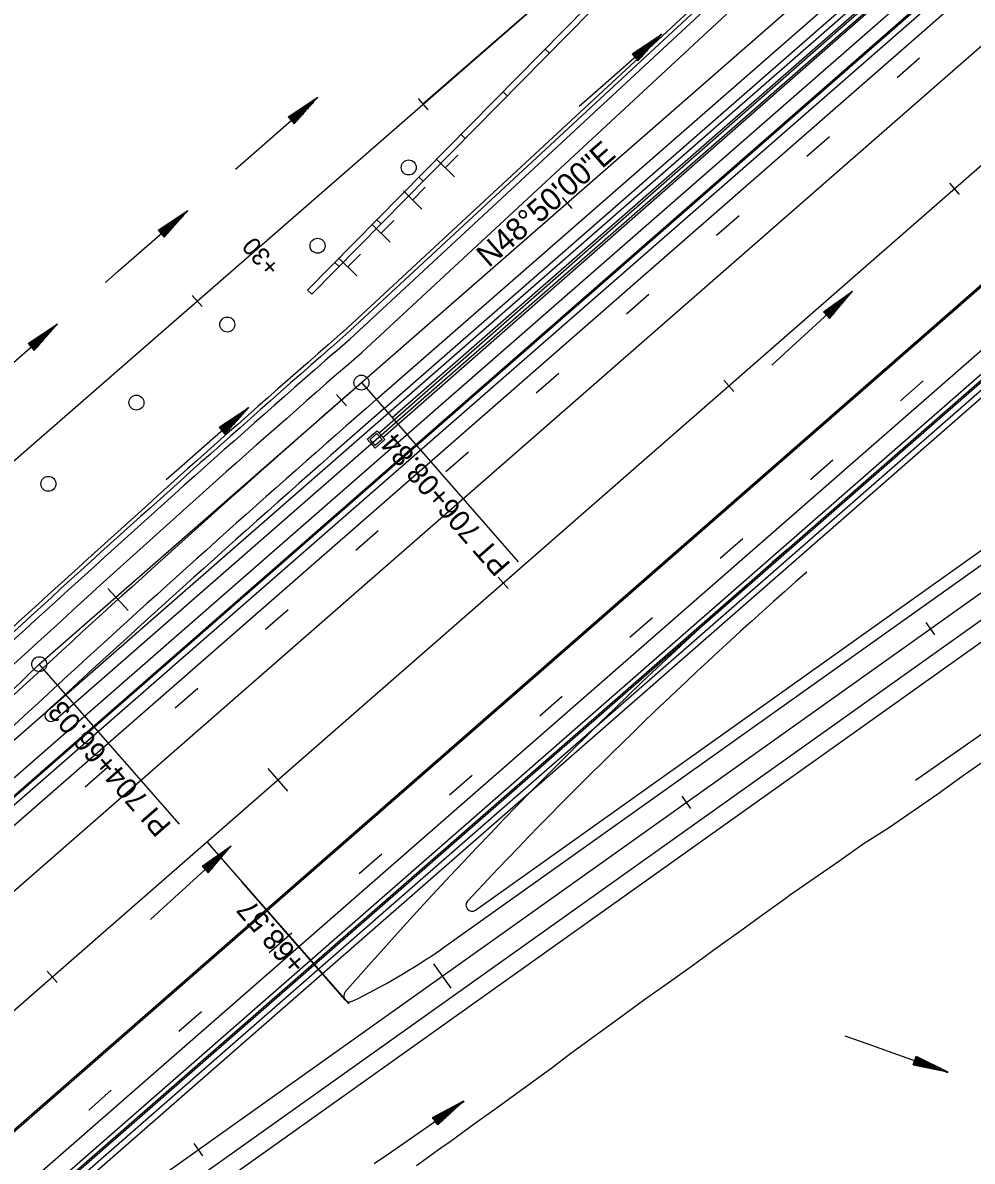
# Model space of a CAD drawing. Extents: x 1300404 to 1323571, y 234004 to 252077.
# Drawn here: x 1309471.7 to 1309788.6, y 239796.9 to 240177.2 of the extents above; entities that cross this region are included whole.
import ezdxf

# ---------------------------------------------------------------- set-up
doc = ezdxf.new("R2010")
doc.units = 0
for name, color, linetype in [('R_Barrel', 7, 'Continuous'), ('R_Barrier Wall', 7, 'Continuous'), ('R_Const Limits', 7, 'Continuous'), ('R_Draft', 7, 'Continuous'), ('R_Drop Inlet', 7, 'Continuous'), ('R_Flow Arrows', 7, 'Continuous'), ('R_Horz Alg Annot', 7, 'Continuous'), ('R_Horz Alg Annot Leader', 7, 'Continuous'), ('R_Horz Alg Major Ticks', 7, 'Continuous'), ('R_Horz Alg Minor Ticks', 7, 'Continuous'), ('R_Horz Alg Tangents', 7, 'Continuous'), ('R_Horz Alg Tangents Text', 7, 'Continuous'), ('R_Lane Edge', 7, 'Continuous'), ('R_Pipe Culvert', 7, 'Continuous'), ('R_Proposed', 7, 'Continuous'), ('R_Shoulder', 7, 'Continuous'), ('R_Temp Barrier Wall', 7, 'Continuous'), ('R_Temp Travel Lane', 7, 'Continuous'), ('R_Temp Travel Stripe', 7, 'Continuous')]:
    doc.layers.add(name, color=color, linetype=linetype)

msp = doc.modelspace()

# ---------------------------------------------------------------- linework, layer by layer
at = {"layer": 'R_Barrel'}
for p, q in [((1309612.7, 240128.71), (1309616.92, 240132.97)), ((1309615.74, 240125.7), (1309609.63, 240131.76)), ((1309604.82, 240114.97), (1309598.71, 240121.03)), ((1309601.78, 240117.99), (1309606, 240122.25)), ((1309594.32, 240103.86), (1309588.21, 240109.91)), ((1309591.28, 240106.87), (1309595.5, 240111.13)), ((1309583.18, 240092.62), (1309577.07, 240098.68)), ((1309580.14, 240095.63), (1309584.36, 240099.89))]:
    msp.add_line(p, q, dxfattribs=at)
for centre in [(1309600.5, 240128.86), (1309570.05, 240102.71), (1309539.93, 240076.4), (1309509.61, 240050.3), (1309480.2, 240023.19)]:
    msp.add_circle(centre, 2.5, dxfattribs=at)
at = {"layer": 'R_Barrier Wall'}
for p, q in [((1309593.62, 240046.84), (1310923.44, 241209.65)), ((1309594.93, 240045.34), (1310924.76, 241208.15)), ((1309578.59, 240073.99), (1309787.17, 240267.71)), ((1309579.5, 240073.02), (1309788.07, 240266.74)), ((1309573.63, 240069.66), (1309578.62, 240074.02)), ((1309574.51, 240068.65), (1309579.5, 240073.02)), ((1309593.62, 240046.84), (1309594.93, 240045.34))]:
    msp.add_line(p, q, dxfattribs=at)
for centre, radius in [((1313356.22, 235743.77), 5746.41), ((1313356.24, 235743.79), 5745.08)]:
    msp.add_arc(centre, radius, 131.166667, 134.023463, dxfattribs=at)
at = {"layer": 'R_Const Limits'}
for points in [[(1309793.39, 239931.15), (1309785.2, 239925.42), (1309777.1, 239919.54), (1309768.93, 239913.79), (1309760.64, 239908.18), (1309752.21, 239902.79), (1309744.02, 239897.05), (1309735.79, 239891.37), (1309727.59, 239885.64), (1309726.44, 239884.81), (1309719.49, 239879.77), (1309711.38, 239873.92), (1309703.27, 239868.07), (1309695.17, 239862.21), (1309687.07, 239856.34), (1309678.89, 239850.58), (1309670.8, 239844.71), (1309662.71, 239838.83), (1309654.64, 239832.92), (1309647.76, 239827.69), (1309646.66, 239826.89), (1309638.6, 239820.97), (1309630.5, 239815.11), (1309622.38, 239809.27), (1309614.27, 239803.42), (1309611.24, 239801.23)], [(1309793.39, 239931.15), (1309785.2, 239925.42), (1309777.1, 239919.54), (1309768.93, 239913.79), (1309760.64, 239908.18), (1309752.21, 239902.79), (1309744.02, 239897.05), (1309735.79, 239891.37), (1309727.59, 239885.64), (1309726.44, 239884.81), (1309719.49, 239879.77), (1309711.38, 239873.92), (1309703.27, 239868.07), (1309695.17, 239862.21), (1309687.07, 239856.34), (1309678.89, 239850.58), (1309670.8, 239844.71), (1309662.71, 239838.83), (1309654.64, 239832.92), (1309647.76, 239827.69), (1309646.66, 239826.89), (1309638.6, 239820.97), (1309630.5, 239815.11), (1309622.38, 239809.27), (1309614.27, 239803.42), (1309613.83, 239803.11)], [(1309611.24, 239801.23), (1309611.24, 239801.23), (1309603.06, 239795.39)]]:
    msp.add_lwpolyline(points, dxfattribs=at)
at = {"layer": 'R_Draft'}
for p, q in [((1308396.96, 238971.92), (1312368.36, 242444.53)), ((1308407.83, 238959.5), (1312379.22, 242432.11)), ((1308447.32, 238914.33), (1312418.71, 242386.94)), ((1308458.18, 238901.91), (1312429.57, 242374.52)), ((1309184.47, 239689.08), (1312131.36, 242265.86)), ((1309037.78, 239548.19), (1312137.61, 242258.71)), ((1309193.69, 239678.54), (1312140.58, 242255.32)), ((1309413.86, 239721.62), (1312065.67, 242040.38)), ((1309410.89, 239725), (1311987.97, 241978.41)), ((1309410.89, 239725), (1311987.97, 241978.41)), ((1309533.11, 239903.6), (1309580.46, 239849.45))]:
    msp.add_line(p, q, dxfattribs=at)
at = {"layer": 'R_Drop Inlet'}
for p, q in [((1309586.67, 240038.06), (1309589.94, 240040.91)), ((1309586.67, 240038.06), (1309589.94, 240040.91)), ((1309589.94, 240040.91), (1309592.52, 240037.95)), ((1309589.94, 240040.91), (1309592.52, 240037.95)), ((1309589.25, 240035.1), (1309586.67, 240038.06)), ((1309589.25, 240035.1), (1309586.67, 240038.06)), ((1309587.61, 240038), (1309589.87, 240039.97)), ((1309587.61, 240038), (1309589.87, 240039.97)), ((1309589.32, 240036.04), (1309587.61, 240038)), ((1309589.32, 240036.04), (1309587.61, 240038)), ((1309592.52, 240037.95), (1309589.25, 240035.1)), ((1309592.52, 240037.95), (1309589.25, 240035.1)), ((1309591.58, 240038.01), (1309589.32, 240036.04)), ((1309591.58, 240038.01), (1309589.32, 240036.04)), ((1309589.87, 240039.97), (1309591.58, 240038.01)), ((1309589.87, 240039.97), (1309591.58, 240038.01))]:
    msp.add_line(p, q, dxfattribs=at)
at = {"layer": 'R_Flow Arrows'}
for p, q in [((1309675.04, 240166.84), (1309684.93, 240173.35)), ((1309677.02, 240164.53), (1309684.93, 240173.35)), ((1309675.04, 240166.84), (1309677.02, 240164.53)), ((1309560.29, 240145.75), (1309570.15, 240152.32)), ((1309562.29, 240143.46), (1309570.15, 240152.32)), ((1309560.29, 240145.75), (1309562.29, 240143.46)), ((1309516.86, 240107.89), (1309526.72, 240114.47)), ((1309518.86, 240105.6), (1309526.72, 240114.47)), ((1309516.86, 240107.89), (1309518.86, 240105.6)), ((1309738.91, 240080.67), (1309748.59, 240087.5)), ((1309740.96, 240078.43), (1309748.59, 240087.5)), ((1309738.91, 240080.67), (1309740.96, 240078.43)), ((1309473.44, 240070.03), (1309483.29, 240076.61)), ((1309475.43, 240067.74), (1309483.29, 240076.61)), ((1309473.44, 240070.03), (1309475.43, 240067.74)), ((1309537.17, 240042.13), (1309547.07, 240048.64)), ((1309539.15, 240039.82), (1309547.07, 240048.64)), ((1309537.17, 240042.13), (1309539.15, 240039.82)), ((1309531.49, 239895.49), (1309541.17, 239902.31)), ((1309533.55, 239893.25), (1309541.17, 239902.31)), ((1309531.49, 239895.49), (1309533.55, 239893.25)), ((1309768.88, 239829.11), (1309769.87, 239831.99)), ((1309769.87, 239831.99), (1309780.49, 239826.73)), ((1309768.88, 239829.11), (1309780.49, 239826.73)), ((1309608.4, 239811.51), (1309618.85, 239817.09)), ((1309610.16, 239809.04), (1309618.85, 239817.09)), ((1309610.16, 239809.04), (1309608.4, 239811.51))]:
    msp.add_line(p, q, dxfattribs=at)
for points in [[(1309657.43, 240149.36), (1309661.75, 240153.18), (1309684.83, 240173.46)], [(1309675.63, 240166.15), (1309680.34, 240170.2), (1309680.98, 240170.74)], [(1309675.83, 240165.92), (1309680.54, 240169.97), (1309682.96, 240172.04)], [(1309676.23, 240165.46), (1309680.94, 240169.51), (1309683.36, 240171.58)], [(1309675.23, 240166.61), (1309677.02, 240168.14)], [(1309675.43, 240166.38), (1309679, 240169.44)], [(1309676.42, 240165.22), (1309681.14, 240169.28), (1309681.77, 240169.82)], [(1309676.62, 240164.99), (1309680.19, 240168.06)], [(1309676.82, 240164.76), (1309678.6, 240166.3)], [(1309542.65, 240128.33), (1309546.98, 240132.13), (1309570.15, 240152.32)], [(1309561.09, 240144.83), (1309565.78, 240148.92), (1309568.18, 240151)], [(1309560.69, 240145.29), (1309564.23, 240148.38)], [(1309560.89, 240145.06), (1309565.58, 240149.15), (1309566.21, 240149.69)], [(1309561.49, 240144.37), (1309566.18, 240148.46), (1309568.58, 240150.54)], [(1309561.69, 240144.15), (1309566.38, 240148.23), (1309567, 240148.78)], [(1309560.49, 240145.52), (1309562.26, 240147.07)], [(1309561.89, 240143.92), (1309565.43, 240147)], [(1309562.09, 240143.69), (1309563.86, 240145.23)], [(1309499.22, 240090.47), (1309503.56, 240094.28), (1309526.72, 240114.47)], [(1309517.66, 240106.97), (1309522.35, 240111.06), (1309524.75, 240113.14)], [(1309517.06, 240107.66), (1309518.83, 240109.21)], [(1309517.26, 240107.43), (1309520.81, 240110.52)], [(1309517.46, 240107.2), (1309522.15, 240111.29), (1309522.78, 240111.84)], [(1309518.06, 240106.52), (1309522.75, 240110.6), (1309525.15, 240112.68)], [(1309518.26, 240106.29), (1309522.95, 240110.37), (1309523.58, 240110.92)], [(1309518.46, 240106.06), (1309522, 240109.15)], [(1309518.66, 240105.83), (1309520.43, 240107.37)], [(1309721.72, 240062.81), (1309725.95, 240066.72), (1309748.59, 240087.5)], [(1309739.32, 240080.23), (1309742.78, 240083.4)], [(1309739.52, 240080), (1309744.11, 240084.21), (1309744.72, 240084.77)], [(1309739.73, 240079.78), (1309744.31, 240083.98), (1309746.66, 240086.13)], [(1309740.14, 240079.33), (1309744.72, 240083.53), (1309747.07, 240085.68)], [(1309740.35, 240079.11), (1309744.93, 240083.31), (1309745.54, 240083.87)], [(1309739.11, 240080.45), (1309740.84, 240082.04)], [(1309740.55, 240078.88), (1309744.02, 240082.06)], [(1309740.76, 240078.66), (1309742.49, 240080.25)], [(1309455.8, 240052.61), (1309460.13, 240056.42), (1309483.29, 240076.61)], [(1309474.24, 240069.12), (1309478.92, 240073.2), (1309481.33, 240075.29)], [(1309473.64, 240069.8), (1309475.41, 240071.35)], [(1309473.84, 240069.57), (1309477.38, 240072.66)], [(1309474.03, 240069.34), (1309478.72, 240073.43), (1309479.35, 240073.98)], [(1309474.63, 240068.66), (1309479.32, 240072.74), (1309481.72, 240074.83)], [(1309474.83, 240068.43), (1309479.52, 240072.51), (1309480.15, 240073.06)], [(1309475.03, 240068.2), (1309478.58, 240071.29)], [(1309475.23, 240067.97), (1309477.01, 240069.51)], [(1309519.57, 240024.65), (1309523.89, 240028.47), (1309546.97, 240048.75)], [(1309537.57, 240041.67), (1309541.13, 240044.73)], [(1309537.76, 240041.44), (1309542.48, 240045.49), (1309543.11, 240046.03)], [(1309537.96, 240041.2), (1309542.68, 240045.26), (1309545.09, 240047.33)], [(1309538.36, 240040.74), (1309543.07, 240044.8), (1309545.49, 240046.87)], [(1309538.56, 240040.51), (1309543.27, 240044.57), (1309543.9, 240045.11)], [(1309537.37, 240041.9), (1309539.15, 240043.43)], [(1309538.76, 240040.28), (1309542.32, 240043.35)], [(1309538.96, 240040.05), (1309540.74, 240041.58)], [(1309769.69, 239924.25), (1309774.43, 239927.54), (1309799.63, 239945.1)], [(1309514.3, 239877.62), (1309518.54, 239881.54), (1309541.17, 239902.31)], [(1309532.31, 239894.59), (1309536.89, 239898.8), (1309539.24, 239900.94)], [(1309532.72, 239894.14), (1309537.3, 239898.35), (1309539.65, 239900.49)], [(1309531.7, 239895.26), (1309533.43, 239896.85)], [(1309531.9, 239895.04), (1309535.36, 239898.22)], [(1309532.11, 239894.81), (1309536.69, 239899.02), (1309537.3, 239899.58)], [(1309532.93, 239893.92), (1309537.51, 239898.12), (1309538.12, 239898.68)], [(1309533.14, 239893.69), (1309536.6, 239896.87)], [(1309533.34, 239893.47), (1309535.07, 239895.06)], [(1309746.06, 239838.83), (1309751.49, 239836.88), (1309780.43, 239826.58)], [(1309769.77, 239831.7), (1309771.99, 239830.94)], [(1309768.98, 239829.4), (1309771.2, 239828.64)], [(1309769.08, 239829.69), (1309773.52, 239828.16)], [(1309769.18, 239829.98), (1309775.06, 239827.95), (1309775.85, 239827.68)], [(1309769.28, 239830.26), (1309775.16, 239828.24), (1309778.17, 239827.21)], [(1309769.47, 239830.84), (1309775.35, 239828.82), (1309778.36, 239827.79)], [(1309769.57, 239831.13), (1309775.45, 239829.1), (1309776.24, 239828.84)], [(1309769.67, 239831.41), (1309774.12, 239829.88)], [(1309588.99, 239796.12), (1309593.73, 239799.4), (1309618.94, 239816.97)], [(1309608.57, 239811.26), (1309610.49, 239812.63)], [(1309608.75, 239811.02), (1309612.58, 239813.74)], [(1309608.93, 239810.77), (1309613.99, 239814.38), (1309614.67, 239814.86)], [(1309609.1, 239810.52), (1309614.17, 239814.13), (1309616.75, 239815.98)], [(1309609.46, 239810.03), (1309614.52, 239813.63), (1309617.11, 239815.49)], [(1309609.63, 239809.78), (1309614.7, 239813.39), (1309615.37, 239813.87)], [(1309609.81, 239809.53), (1309613.64, 239812.26)], [(1309609.99, 239809.28), (1309611.9, 239810.65)]]:
    msp.add_lwpolyline(points, dxfattribs=at)
at = {"layer": 'R_Horz Alg Annot Leader'}
for q in [(1309544.76, 239890.27), (1309558.71, 239874.31)]:
    msp.add_line((1309579.27, 239850.81), q, dxfattribs=at)
for points in [[(1309584.71, 240056.98), (1309637.02, 239997.16)], [(1309584.71, 240056.98), (1309637.02, 239997.16)], [(1309523.93, 239909.45), (1309477.16, 239962.94)], [(1309523.93, 239909.45), (1309477.16, 239962.94)]]:
    msp.add_lwpolyline(points, dxfattribs=at)
at = {"layer": 'R_Horz Alg Major Ticks'}
for points in [[(1309500.1, 239988.27), (1309506.82, 239980.87)], [(1309500.1, 239988.27), (1309506.82, 239980.87)], [(1309553.48, 239928.05), (1309560.06, 239920.53)], [(1309553.48, 239928.05), (1309560.06, 239920.53)], [(1309608.77, 239862.86), (1309614.57, 239854.71)], [(1309608.77, 239862.86), (1309614.57, 239854.71)]]:
    msp.add_lwpolyline(points, dxfattribs=at)
at = {"layer": 'R_Horz Alg Minor Ticks'}
for points in [[(1309603.59, 240151.85), (1309606.87, 240148.09)], [(1309603.59, 240151.85), (1309606.87, 240148.09)], [(1309780.96, 240123.65), (1309784.26, 240119.88)], [(1309780.96, 240123.65), (1309784.26, 240119.88)], [(1309651.69, 240118.87), (1309654.98, 240115.11)], [(1309651.69, 240118.87), (1309654.98, 240115.11)], [(1309528.21, 240086.14), (1309531.49, 240082.37)], [(1309528.21, 240086.14), (1309531.49, 240082.37)], [(1309705.68, 240057.82), (1309708.98, 240054.06)], [(1309705.68, 240057.82), (1309708.98, 240054.06)], [(1309576.41, 240053.04), (1309579.71, 240049.28)], [(1309576.41, 240053.04), (1309579.71, 240049.28)], [(1309630.4, 239992), (1309633.7, 239988.23)], [(1309630.4, 239992), (1309633.7, 239988.23)], [(1309773.13, 239976.84), (1309776.03, 239972.77)], [(1309773.13, 239976.84), (1309776.03, 239972.77)], [(1309691.67, 239918.83), (1309694.57, 239914.76)], [(1309691.67, 239918.83), (1309694.57, 239914.76)], [(1309479.84, 239860.35), (1309483.14, 239856.58)], [(1309479.84, 239860.35), (1309483.14, 239856.58)], [(1309528.76, 239802.81), (1309531.66, 239798.74)], [(1309528.76, 239802.81), (1309531.66, 239798.74)]]:
    msp.add_lwpolyline(points, dxfattribs=at)
at = {"layer": 'R_Horz Alg Tangents'}
for p, q in [((1309477.16, 239962.94), (1309584.71, 240056.98)), ((1309477.16, 239962.94), (1309584.71, 240056.98)), ((1309374.43, 239863.65), (1309477.16, 239962.94)), ((1309374.43, 239863.65), (1309477.16, 239962.94))]:
    msp.add_line(p, q, dxfattribs=at)
at = {"layer": 'R_Lane Edge'}
for p, q in [((1309254.07, 239731.34), (1311026.82, 241281.45)), ((1309254.07, 239731.34), (1311026.82, 241281.45)), ((1309589.67, 240051.36), (1310894.61, 241192.4)), ((1309584.85, 240067.07), (1309804.77, 240271.32)), ((1309579.77, 240062.63), (1309584.85, 240067.07)), ((1309611.37, 239867.78), (1309830.38, 240023.76)), ((1309374.62, 239680.75), (1309839.08, 240011.54))]:
    msp.add_line(p, q, dxfattribs=at)
for centre, radius, start, end in [((1313356.24, 235743.79), 5737.08, 131.166667, 134.023463), ((1313356.22, 235743.77), 5722.08, 131.16667, 134.02346), ((1313356.22, 235743.77), 5722.08, 131.16667, 134.02346), ((1310770.2, 238812.1), 1582, 131.26805, 138.83378), ((1309486.73, 240046.02), 217.5, 295.8741, 304.9655), ((1309580.77, 239852.13), 2, 138.8331, 295.8874)]:
    msp.add_arc(centre, radius, start, end, dxfattribs=at)
at = {"layer": 'R_Pipe Culvert'}
for p, q in [((1309590.57, 240040.19), (1310077.98, 240468.2)), ((1309590.57, 240040.19), (1310077.98, 240468.2)), ((1309590.57, 240040.19), (1310077.98, 240468.2)), ((1309591.88, 240038.68), (1310079.3, 240466.69)), ((1309591.88, 240038.68), (1310079.3, 240466.69)), ((1309591.88, 240038.68), (1310079.3, 240466.69))]:
    msp.add_line(p, q, dxfattribs=at)
at = {"layer": 'R_Proposed'}
for p, q in [((1308427.57, 238936.91), (1312793.8, 242754.77)), ((1308427.57, 238936.91), (1312793.8, 242754.77)), ((1309180.37, 239595.16), (1312398.96, 242409.52)), ((1309180.37, 239595.16), (1312398.96, 242409.52)), ((1309584.71, 240056.98), (1310889.67, 241198.05)), ((1309584.71, 240056.98), (1310889.67, 241198.05)), ((1309454.47, 240018.55), (1309644.99, 240184.63)), ((1309454.47, 240018.55), (1309644.99, 240184.63)), ((1309644.99, 240184.63), (1309605.23, 240149.97)), ((1309644.99, 240184.63), (1309605.23, 240149.97)), ((1309370.27, 239686.86), (1309834.73, 240017.65)), ((1309370.27, 239686.86), (1309834.73, 240017.65)), ((1309370.27, 239686.86), (1309834.73, 240017.65)), ((1309370.27, 239686.86), (1309834.73, 240017.65)), ((1309370.27, 239686.86), (1309834.73, 240017.65)), ((1309370.27, 239686.86), (1309834.73, 240017.65))]:
    msp.add_line(p, q, dxfattribs=at)
for centre in [(1309584.71, 240056.98), (1309584.71, 240056.98), (1309477.16, 239962.94), (1309477.16, 239962.94)]:
    msp.add_circle(centre, 2.5, dxfattribs=at)
msp.add_arc((1313356.22, 235743.77), 5729.58, 131.166667, 134.023463, dxfattribs=at)
msp.add_arc((1313356.22, 235743.77), 5729.58, 131.166667, 134.023463, dxfattribs=at)
at = {"layer": 'R_Shoulder'}
for p, q in [((1309482.39, 239944.26), (1311020.24, 241288.97)), ((1309482.39, 239944.26), (1311020.24, 241288.97)), ((1309592.3, 240048.35), (1310897.24, 241189.39)), ((1309580.84, 240071.53), (1309800.75, 240275.78)), ((1309575.82, 240067.15), (1309580.84, 240071.53)), ((1309622.76, 239880.8), (1309828.06, 240027.02)), ((1309378.1, 239675.87), (1309842.57, 240006.66))]:
    msp.add_line(p, q, dxfattribs=at)
for centre, radius, start, end in [((1313356.24, 235743.79), 5743.08, 131.166667, 134.023463), ((1313356.24, 235743.79), 5718.08, 131.16667, 132.68298), ((1313356.24, 235743.79), 5718.08, 131.16667, 132.68298), ((1310770.2, 238812.1), 1572, 131.26805, 137.02024), ((1309481.07, 239945.77), 2, 132.683, 311.1667), ((1309481.07, 239945.77), 2, 132.683, 311.1667), ((1309621.6, 239882.43), 2, 137.0202, 305.4583)]:
    msp.add_arc(centre, radius, start, end, dxfattribs=at)
at = {"layer": 'R_Temp Barrier Wall'}
for p, q in [((1309216.25, 239554.17), (1310194.9, 240409.84)), ((1309217.56, 239552.67), (1310196.22, 240408.33)), ((1309566.7, 240087.91), (1309660.05, 240182.65)), ((1309568.12, 240086.51), (1309661.47, 240181.25)), ((1309647.44, 240167), (1309646.01, 240168.4)), ((1309633.4, 240152.75), (1309631.97, 240154.16)), ((1309619.36, 240138.51), (1309617.94, 240139.91)), ((1309605.32, 240124.26), (1309603.9, 240125.67)), ((1309591.29, 240110.02), (1309589.86, 240111.42)), ((1309577.25, 240095.77), (1309575.82, 240097.17)), ((1309566.7, 240087.91), (1309568.12, 240086.51))]:
    msp.add_line(p, q, dxfattribs=at)
for points in [[(1311027.31, 241280.88), (1310559.74, 240872.07), (1309471.94, 239921.22), (1308468.86, 239041.61)], [(1311028.63, 241279.38), (1310561.08, 240870.59), (1309473.28, 239919.73), (1308470.17, 239040.11)]]:
    msp.add_lwpolyline(points, dxfattribs=at)
at = {"layer": 'R_Temp Travel Lane'}
for p, q in [((1309139.54, 239489.78), (1310268.87, 240477.17)), ((1309125.14, 239506.41), (1309953.25, 240230.44)), ((1309125.06, 239506.34), (1309935.81, 240215.2))]:
    msp.add_line(p, q, dxfattribs=at)
at = {"layer": 'R_Temp Travel Stripe'}
for p, q in [((1309771.03, 240165.39), (1309763.5, 240158.81)), ((1309740.91, 240139.07), (1309733.38, 240132.49)), ((1309710.8, 240112.74), (1309703.27, 240106.16)), ((1309680.68, 240086.42), (1309673.15, 240079.84)), ((1309650.56, 240060.09), (1309643.04, 240053.51)), ((1309764.68, 240050.96), (1309772.21, 240057.54)), ((1309620.45, 240033.77), (1309612.92, 240027.19)), ((1309734.57, 240024.63), (1309742.09, 240031.21)), ((1309590.33, 240007.44), (1309582.8, 240000.86)), ((1309704.45, 239998.3), (1309711.98, 240004.89)), ((1309560.22, 239981.12), (1309552.69, 239974.54)), ((1309674.34, 239971.97), (1309681.87, 239978.56)), ((1309530.1, 239954.79), (1309522.57, 239948.21)), ((1309644.23, 239945.65), (1309651.75, 239952.23)), ((1309499.98, 239928.47), (1309492.45, 239921.89)), ((1309614.11, 239919.32), (1309621.64, 239925.9)), ((1309584, 239892.99), (1309591.53, 239899.57)), ((1309553.89, 239866.66), (1309561.42, 239873.24)), ((1309523.77, 239840.33), (1309531.3, 239846.91)), ((1309493.66, 239814), (1309501.19, 239820.59))]:
    msp.add_line(p, q, dxfattribs=at)

# ---------------------------------------------------------------- texts
at = {"layer": 'R_Horz Alg Annot'}
for s, rotation, p in [('PT 706+08.84', 131.1667, (1309634.8, 239996.3)), ('PT 706+08.84', 131.1667, (1309634.8, 239996.3)), ('PI 704+66.03', 131.1667, (1309521.58, 239909.24)), ('PI 704+66.03', 131.1667, (1309521.58, 239909.24)), ('+68.57', 130.5769, (1309566.68, 239863.17))]:
    msp.add_text(s, height=7, rotation=rotation, dxfattribs=at).set_placement(p)
at = {"layer": 'R_Horz Alg Tangents Text'}
msp.add_text('N48%%d50\'00"E', height=7.5, rotation=41.1667, dxfattribs=at).set_placement((1309627.22, 240095.21))
msp.add_text('N48%%d50\'00"E', height=7.5, rotation=41.1667, dxfattribs=at).set_placement((1309627.22, 240095.21))
at = {"layer": 'R_Temp Barrier Wall'}
msp.add_text('+30', height=6, rotation=130.9255, dxfattribs=at).set_placement((1309557.87, 240095.83))

doc.saveas('drawing.dxf')
